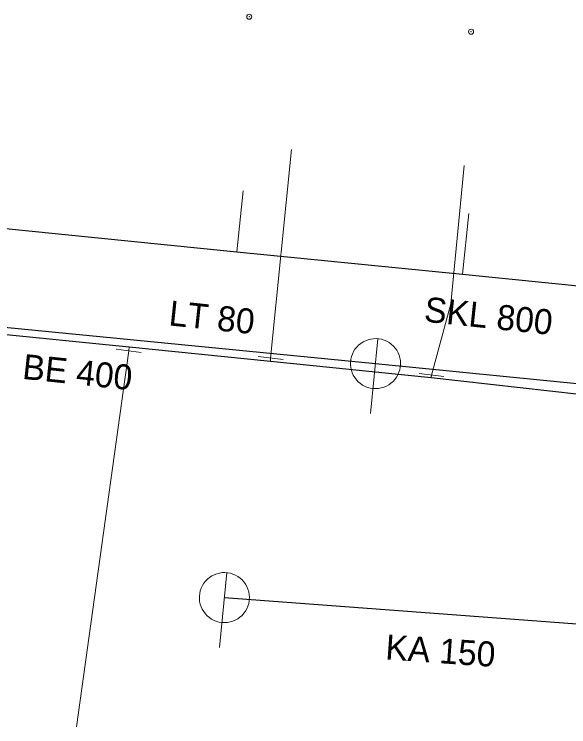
# Model space of a CAD drawing. Extents: x -783064 to -782702, y -1007904 to -1007145.
# Drawn here: x -782972.33 to -782950.19, y -1007412.26 to -1007383.79 of the extents above; entities that cross this region are included whole.
import ezdxf

# ---------------------------------------------------------------- set-up
doc = ezdxf.new("R2010")
doc.units = 0
doc.header["$LTSCALE"] = 0.4
doc.header["$PDMODE"] = 32
doc.header["$PDSIZE"] = 0.2
for name, color, linetype, lineweight in [('1', 7, 'Continuous', 13), ('11', 7, 'Continuous', 13), ('13', 7, 'Continuous', 13), ('14', 7, 'Continuous', 13), ('17', 7, 'Continuous', 25), ('22', 7, 'Continuous', 13), ('34', 7, 'Continuous', 13)]:
    doc.layers.add(name, color=color, linetype=linetype, lineweight=lineweight)

msp = doc.modelspace()

# ---------------------------------------------------------------- linework, layer by layer
at = {"layer": '1'}
for p in [(-782962.949, -1007383.889), (-782954.09, -1007384.489)]:
    msp.add_point(p, dxfattribs=at)
at = {"layer": '11'}
for p, q in [((-782963.19, -1007390.85), (-782963.44, -1007393.28)), ((-782954.18, -1007391.75), (-782954.43, -1007394.18))]:
    msp.add_line(p, q, dxfattribs=at)
at = {"layer": '13'}
for p, q in [((-782962.094, -1007397.527), (-782961.261, -1007389.189)), ((-782967.761, -1007397.238), (-782969.846, -1007412.263)), ((-782962.096, -1007397.571), (-782962.094, -1007397.527))]:
    msp.add_line(p, q, dxfattribs=at)
msp.add_lwpolyline([(-782955.669, -1007398.209), (-782954.899, -1007395.36), (-782954.37, -1007389.84)], dxfattribs=at)
at = {"layer": '14'}
for p, q in [((-782967.743, -1007397.085), (-782967.761, -1007397.238)), ((-782955.68, -1007398.31), (-782955.669, -1007398.209))]:
    msp.add_line(p, q, dxfattribs=at)
at = {"layer": '14', "lineweight": 25}
msp.add_line((-782963.94, -1007407.1), (-782944.85, -1007408.53), dxfattribs=at)
for points in [[(-782983.228, -1007391.299), (-782974.833, -1007392.137), (-782973.21, -1007392.3), (-782963.44, -1007393.28), (-782954.43, -1007394.18), (-782945.989, -1007395.03), (-782935.15, -1007396.194), (-782929.789, -1007396.77)], [(-782979.802, -1007395.6), (-782957.907, -1007397.75), (-782930.949, -1007400.43)]]:
    msp.add_lwpolyline(points, dxfattribs=at)
at = {"layer": '14'}
msp.add_lwpolyline([(-782962.101, -1007397.658), (-782962.096, -1007397.571), (-782962.094, -1007397.527)], dxfattribs=at)
at = {"layer": '17'}
msp.add_lwpolyline([(-782999.155, -1007394.238), (-782995.359, -1007394.53), (-782986.82, -1007395.16), (-782986.309, -1007395.2), (-782981.552, -1007395.683), (-782973.329, -1007396.518), (-782967.743, -1007397.085), (-782962.101, -1007397.658), (-782955.68, -1007398.31), (-782946.21, -1007399.37), (-782941.319, -1007399.909)], dxfattribs=at)
at = {"layer": '22'}
for p, q in [((-782958.104, -1007399.74), (-782957.808, -1007396.755)), ((-782964.129, -1007409.091), (-782963.845, -1007406.104))]:
    msp.add_line(p, q, dxfattribs=at)
for points in [[(-782956.911, -1007397.849), (-782956.907, -1007397.74), (-782956.914, -1007397.631), (-782956.933, -1007397.522), (-782956.963, -1007397.418), (-782957.005, -1007397.316), (-782957.058, -1007397.22), (-782957.121, -1007397.131), (-782957.194, -1007397.049), (-782957.275, -1007396.975), (-782957.363, -1007396.911), (-782957.458, -1007396.856), (-782957.559, -1007396.813), (-782957.663, -1007396.78), (-782957.771, -1007396.76), (-782957.881, -1007396.751), (-782957.989, -1007396.754), (-782958.098, -1007396.768), (-782958.205, -1007396.795), (-782958.307, -1007396.834), (-782958.404, -1007396.883), (-782958.497, -1007396.943), (-782958.581, -1007397.012), (-782958.658, -1007397.09), (-782958.726, -1007397.176), (-782958.783, -1007397.269), (-782958.83, -1007397.368), (-782958.867, -1007397.472), (-782958.891, -1007397.578), (-782958.904, -1007397.687), (-782958.905, -1007397.796), (-782958.895, -1007397.905), (-782958.871, -1007398.012), (-782958.837, -1007398.116), (-782958.792, -1007398.216), (-782958.735, -1007398.31), (-782958.669, -1007398.397), (-782958.594, -1007398.477), (-782958.51, -1007398.547), (-782958.42, -1007398.608), (-782958.323, -1007398.659), (-782958.221, -1007398.7), (-782958.115, -1007398.728), (-782958.006, -1007398.745), (-782957.897, -1007398.75), (-782957.788, -1007398.743), (-782957.681, -1007398.724), (-782957.575, -1007398.693), (-782957.474, -1007398.651), (-782957.378, -1007398.598), (-782957.288, -1007398.536), (-782957.206, -1007398.464), (-782957.132, -1007398.383), (-782957.067, -1007398.295), (-782957.014, -1007398.2), (-782956.97, -1007398.099), (-782956.937, -1007397.994), (-782956.916, -1007397.887)], [(-782962.944, -1007407.195), (-782962.94, -1007407.086), (-782962.947, -1007406.976), (-782962.967, -1007406.868), (-782962.997, -1007406.764), (-782963.04, -1007406.662), (-782963.093, -1007406.567), (-782963.157, -1007406.477), (-782963.23, -1007406.396), (-782963.311, -1007406.322), (-782963.399, -1007406.258), (-782963.495, -1007406.204), (-782963.596, -1007406.161), (-782963.7, -1007406.129), (-782963.808, -1007406.109), (-782963.918, -1007406.101), (-782964.027, -1007406.104), (-782964.135, -1007406.119), (-782964.242, -1007406.146), (-782964.344, -1007406.186), (-782964.441, -1007406.235), (-782964.533, -1007406.295), (-782964.617, -1007406.365), (-782964.694, -1007406.444), (-782964.761, -1007406.53), (-782964.818, -1007406.623), (-782964.865, -1007406.722), (-782964.901, -1007406.826), (-782964.925, -1007406.932), (-782964.937, -1007407.041), (-782964.938, -1007407.151), (-782964.927, -1007407.259), (-782964.903, -1007407.366), (-782964.869, -1007407.47), (-782964.823, -1007407.569), (-782964.766, -1007407.663), (-782964.7, -1007407.75), (-782964.624, -1007407.829), (-782964.54, -1007407.9), (-782964.449, -1007407.961), (-782964.352, -1007408.011), (-782964.25, -1007408.051), (-782964.144, -1007408.079), (-782964.035, -1007408.095), (-782963.926, -1007408.1), (-782963.817, -1007408.092), (-782963.71, -1007408.073), (-782963.604, -1007408.042), (-782963.503, -1007407.999), (-782963.407, -1007407.946), (-782963.318, -1007407.883), (-782963.236, -1007407.811), (-782963.163, -1007407.729), (-782963.098, -1007407.641), (-782963.045, -1007407.546), (-782963.001, -1007407.445), (-782962.969, -1007407.34), (-782962.949, -1007407.232)]]:
    msp.add_lwpolyline(points, close=True, dxfattribs=at)
at = {"layer": '34'}
for p, q in [((-782968.257, -1007397.175), (-782967.265, -1007397.301)), ((-782962.59, -1007397.464), (-782961.598, -1007397.59)), ((-782956.165, -1007398.146), (-782955.173, -1007398.272))]:
    msp.add_line(p, q, dxfattribs=at)

# ---------------------------------------------------------------- texts
at = {"layer": '1'}
for s, rotation, p in [('LT 80 ', 354, (-782966.188, -1007396.219)), ('SKL 800 ', 354, (-782955.995, -1007396.07)), ('BE 400', 354, (-782972.034, -1007398.357)), ('KA 150', 356, (-782957.533, -1007409.57))]:
    msp.add_text(s, height=1, rotation=rotation, dxfattribs=at).set_placement(p)

doc.saveas('drawing.dxf')
